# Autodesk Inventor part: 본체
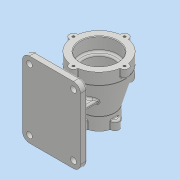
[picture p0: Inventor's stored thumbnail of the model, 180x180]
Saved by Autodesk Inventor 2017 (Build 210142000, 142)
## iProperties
Part Number: 본체
Material: 일반
Document SubType Name: Modeling
Designer: 222
Density: 1 g/cm^3
Appearance: 기본값
Author: 222
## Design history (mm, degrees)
sketch "스케치2"
  geometry: L1 (0, 0)-(44, 0); L2 (44, 0)-(44, -20); L3 (44, -20)-(27.5, -78); L4 (27.5, -78)-(27.5, -100); L5 (27.5, -100)-(0, -100); L6 (0, -100)-(0, 0)
  constraints: 12 end point, 3 perpendicular, 1 horizontal, 1 parallel
  dimensions: "d0" = 88 diameter of L2 L6; "d1" = 55 diameter of L4 L6; "d2" = 100 distance of L5.end L1.start; "d4" = 20 distance of L1.end L2.end; "d5" = 22 distance of L3.end L4.end
revolve "회전1" sketch "스케치2" stored, may be unused: angle "d6" = 90 deg
node "작업 평면1"
sketch "스케치3"
  geometry: L1 (50, 15)-(-50, 15); L2 (-50, 15)-(-50, -115); L3 (-50, -115)-(50, -115); L4 (50, -115)-(50, 15); L5 (-44, 0)-(44, 0) reference; 2 further points
  constraints: 8 end point, 2 parallel, 1 horizontal, 1 midpoint, 1 perpendicular, 1 vertical alignment
  dimensions: "d8" = 130 distance of L3.end L1.start; "d9" = 100 distance of L2.end L3.end; "d10" = 15 distance between parallel lines of L1 L5
extrude "돌출1" join sketch "스케치3" distance "d11" = 12; taper "d12" = 0 deg
sketch "스케치6"
  geometry: L1 (-50, -15)-(50, -15) reference; L2 (-50, 115)-(-50, -15) reference; L3 (50, 115)-(-50, 115) reference; L4 (50, -15)-(50, 115) reference; L5 (-25, 46)-(25, 46); L6 (25, 46)-(25, 54); L7 (25, 54)-(-25, 54); L8 (-25, 54)-(-25, 46); L9 (-4, 26)-(4, 26); L10 (4, 26)-(4, 74); L11 (4, 74)-(-4, 74); L12 (-4, 74)-(-4, 26); 6 further points
  constraints: 16 end point, 5 midpoint, 4 parallel, 2 horizontal, 2 horizontal alignment, 2 perpendicular, 2 vertical alignment
  dimensions: "d15" = 8 distance of L7.end L5.start; "d16" = 8 distance of L10.end L11.end; "d17" = 48 distance of L9.end L10.end; "d18" = 50 distance of L6.end L7.end
extrude "돌출2" join sketch "스케치6" stored distance "d19" = 12; taper "d20" = 0 deg
sketch "스케치7"
  geometry: L1 (-7, 43.44)-(-7, 44); L2 (7, 44)-(7, 43.44); A1 r 44 centre (0, 0) between (-7, 43.44) and (7, 43.44) reference; A2 r 7 centre (0, 44) between (7, 44) and (-7, 44); 1 further point
  constraints: 5 point on circle, 4 end point, 2 tangent, 1 centre point, 1 parallel, 1 vertical, 1 vertical alignment
  dimensions: "d21" = 7 radius of A2
extrude "돌출3" join sketch "스케치7" distance "d22" = 15; taper "d23" = 0 deg
sketch "스케치8"
  geometry: L1 (-7, 26.594)-(-7, 27.5); L2 (7, 27.5)-(7, 26.594); A1 r 27.5 centre (0, 0) between (-7, 26.594) and (7, 26.594) reference; A2 r 7 centre (0, 27.5) between (7, 27.5) and (-7, 27.5); 1 further point
  constraints: 5 point on circle, 4 end point, 2 tangent, 2 vertical, 1 centre point, 1 vertical alignment
  dimensions: "d27" = 7 radius of A2
extrude "돌출4" join sketch "스케치8" distance "d28" = 15; taper "d29" = 0 deg
node "작업 평면2"
sketch "스케치9"
  geometry: L1 (7, 0)-(-7, 0) reference; C1 r 17 at (0, -50); 2 further points
  constraints: 1 centre point, 1 midpoint, 1 vertical alignment
  dimensions: "d34" = 34 diameter of C1; "d35" = 50 distance from line of C1.centre L1
extrude "돌출5" join sketch "스케치9" stored distance "d36" = 15; taper "d37" = 0 deg
hole "구멍1" diameter "d40" = 52; stored, may be unused: countersink angle "d44" = 90 deg, drill point angle "d46" = 0 deg; dims "d38" = 10, "d39" = 10, "d41" = 6, "d42" = 64, "d43" = 23, "d45" = 70
hole "구멍2" diameter "d49" = 40; stored, may be unused: countersink angle "d53" = 90 deg, drill point angle "d55" = 0 deg; dims "d47" = 10, "d48" = 10, "d50" = 6, "d51" = 20, "d52" = 23, "d54" = 30
hole "구멍3" diameter "d58" = 22; stored, may be unused: countersink angle "d62" = 90 deg, drill point angle "d64" = 0 deg; dims "d56" = 10, "d57" = 10, "d59" = 6, "d60" = 28, "d61" = 1, "d63" = 30
sketch "스케치10"
  geometry: A1 r 44 centre (0, -44) between (7, -0.56) and (-7, -0.56) reference; 3 further points
  constraints: 1 coincident, 1 point on circle, 1 vertical alignment
hole "구멍4" sketch "스케치10" at (0, 0) diameter "d65" = 4.134; stored, may be unused: countersink angle "d69" = 90 deg, drill point angle "d71" = 118 deg; dims "d66" = 9, "d67" = 28, "d68" = 1, "d70" = 11
sketch "스케치11"
  geometry: A1 r 27.5 centre (0, -27.5) between (7, -0.906) and (-7, -0.906) reference; 3 further points
  constraints: 1 coincident, 1 point on circle, 1 vertical alignment
hole "구멍5" sketch "스케치11" at (0, 0) diameter "d75" = 4.134; stored, may be unused: countersink angle "d79" = 90 deg, drill point angle "d81" = 118 deg; dims "d76" = 9, "d77" = 28, "d78" = 1, "d80" = 11
sketch "스케치12"
  geometry: L1 (50, -15)-(50, 115) reference; L2 (50, 115)-(-50, 115) reference; 2 further points
  constraints: 1 other
  dimensions: "d85" = 10 distance from line of point (40, 50) L1; "d86" = 65 distance from line of point (40, 50) L2
feature "엠보싱1" sketch "스케치12" dims "d0" = 88, "d1" = 55, "d2" = 100, "d4" = 20, "d5" = 22, "d87" = 0.5, "d88" = 0
fillet "모깎기1" dims "d89" = 12
sketch "스케치13"
  geometry: L1 (-50, 103)-(-50, -3) reference; L2 (38, 115)-(-38, 115) reference; L3 (50, -3)-(50, 103) reference; L4 (-38, -15)-(38, -15) reference; A1 r 12 centre (-38, -3) between (-50, -3) and (-38, -15) reference; A2 r 12 centre (-38, 103) between (-38, 115) and (-50, 103) reference; A3 r 12 centre (38, 103) between (50, 103) and (38, 115) reference; A4 r 12 centre (38, -3) between (38, -15) and (50, -3) reference; 5 further points
  constraints: 4 coincident
hole "구멍6" sketch "스케치13" at (-38, -3), (-38, 103), (38, -3), (38, 103) diameter "d90" = 10; stored, may be unused: countersink angle "d94" = 90 deg, drill point angle "d96" = 0 deg; dims "d91" = 9, "d92" = 28, "d93" = 1, "d95" = 11
fillet "모깎기2" dims "d97" = 3
fillet "모깎기3" dims "d98" = 3
fillet "모깎기4" dims "d99" = 1
fillet "모깎기5" dims "d100" = 3
chamfer "모따기1" distance "d101" = 1; stored, may be unused: second distance "d102" = 2, angle "d103" = 45 deg
node "솔리드1"
pattern_circular "원형 패턴1" dims angle "d25" = 360 deg
pattern_circular "원형 패턴2" dims angle "d31" = 360 deg
pattern_circular "원형 패턴3" dims angle "d73" = 360 deg
pattern_circular "원형 패턴4" dims angle "d83" = 360 deg
node "투영된 루프1"
node "투영된 루프2"
node "투영된 루프3"
other parameters: "d7" = -82, "d33" = 45
